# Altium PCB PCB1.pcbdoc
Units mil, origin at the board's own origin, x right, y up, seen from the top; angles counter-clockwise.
Board outline 2952.76 x 2952.76 mil, 2 copper layers (Top Layer, Bottom Layer), stack 62.206 mil thick; 24 components, 35 nets, 97 pads, 20 vias.
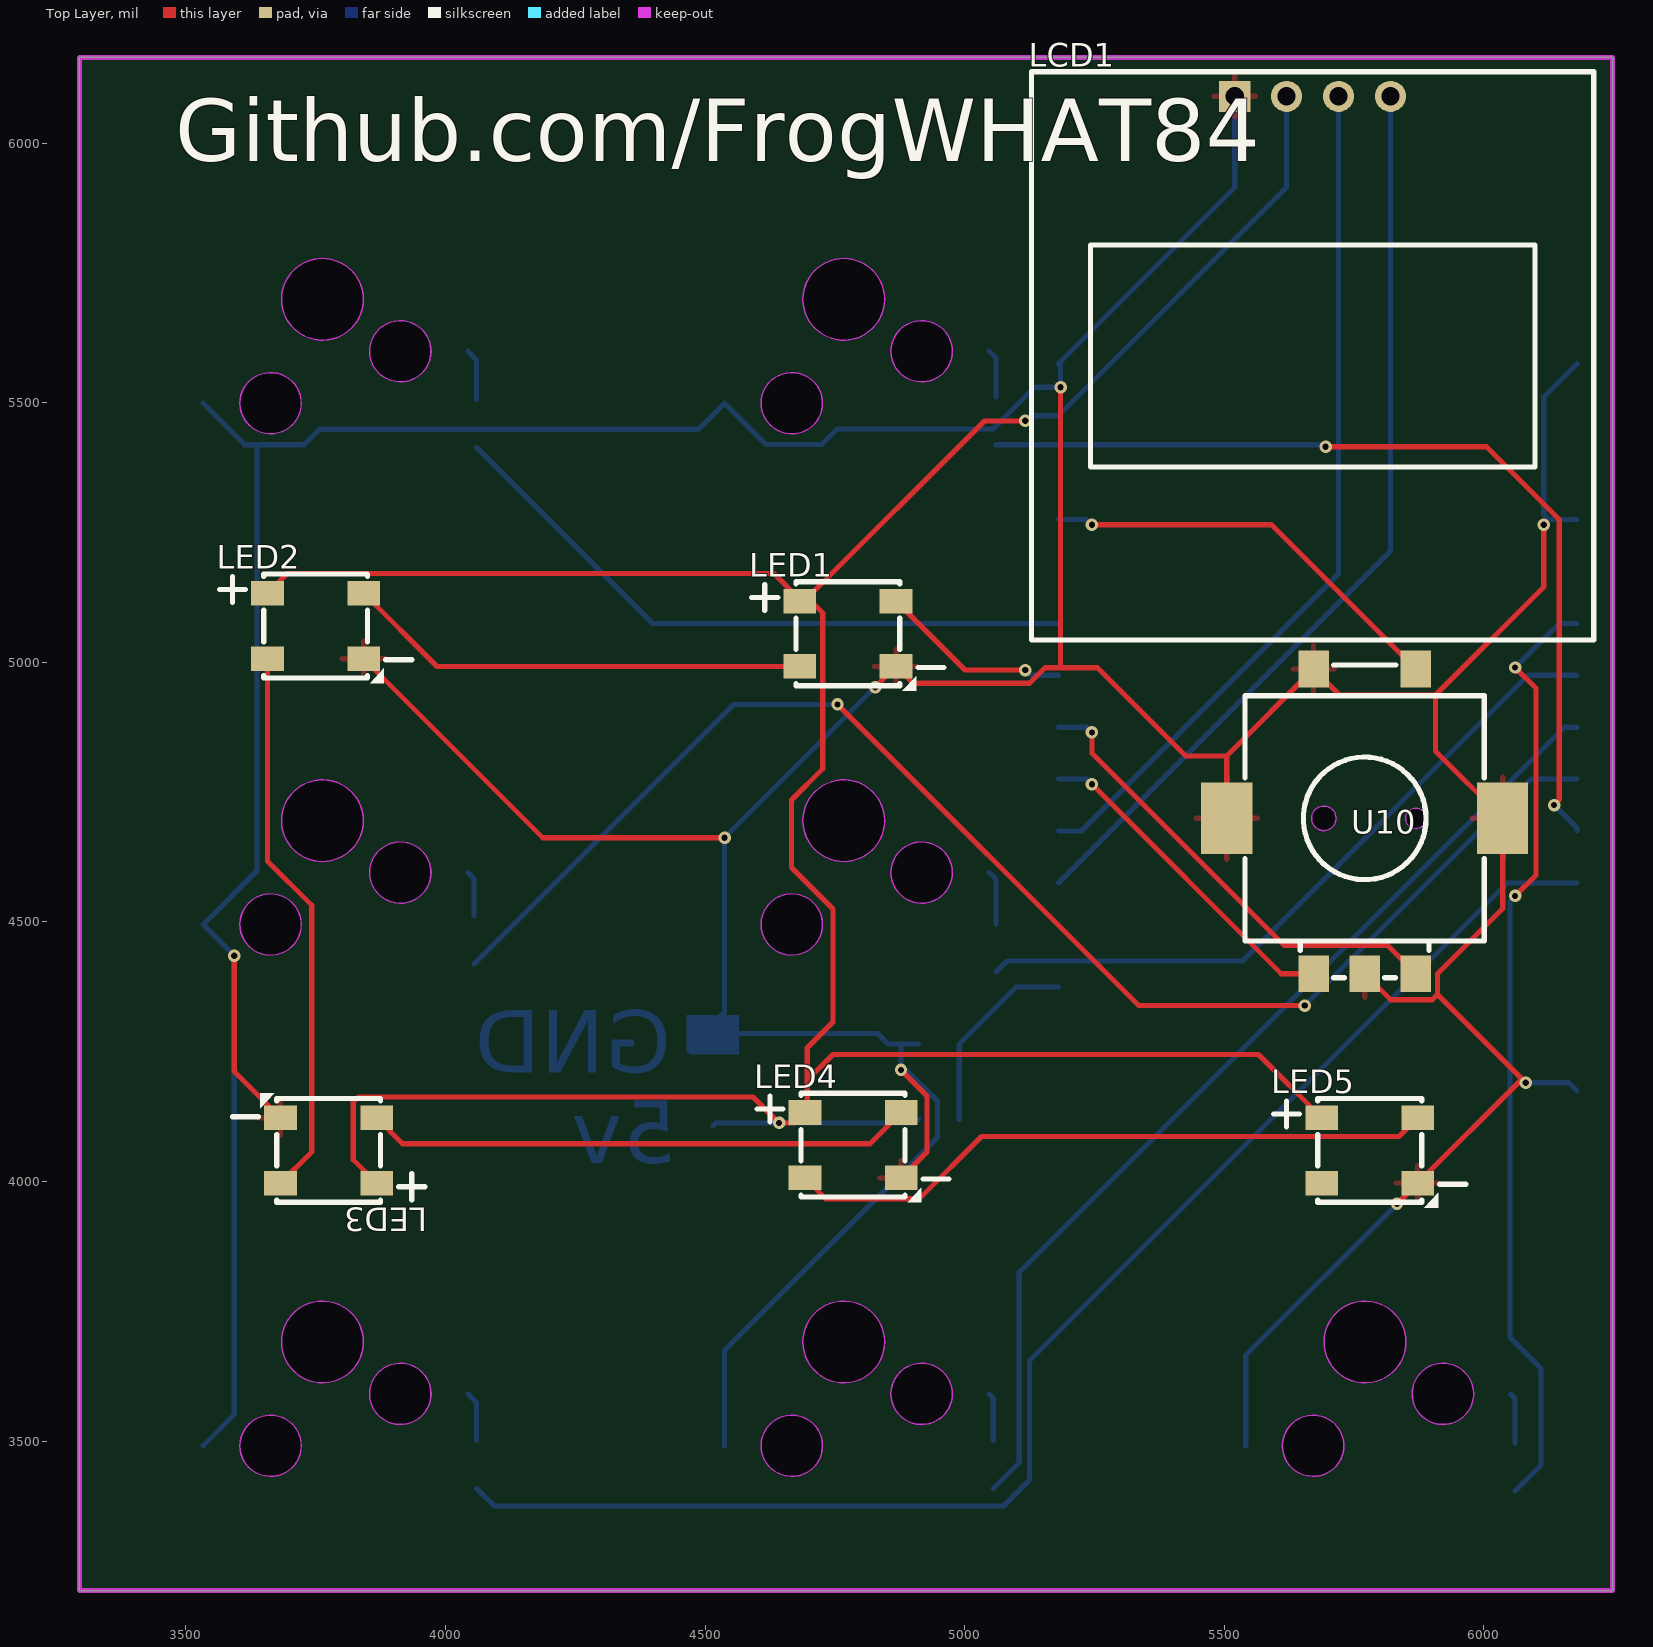
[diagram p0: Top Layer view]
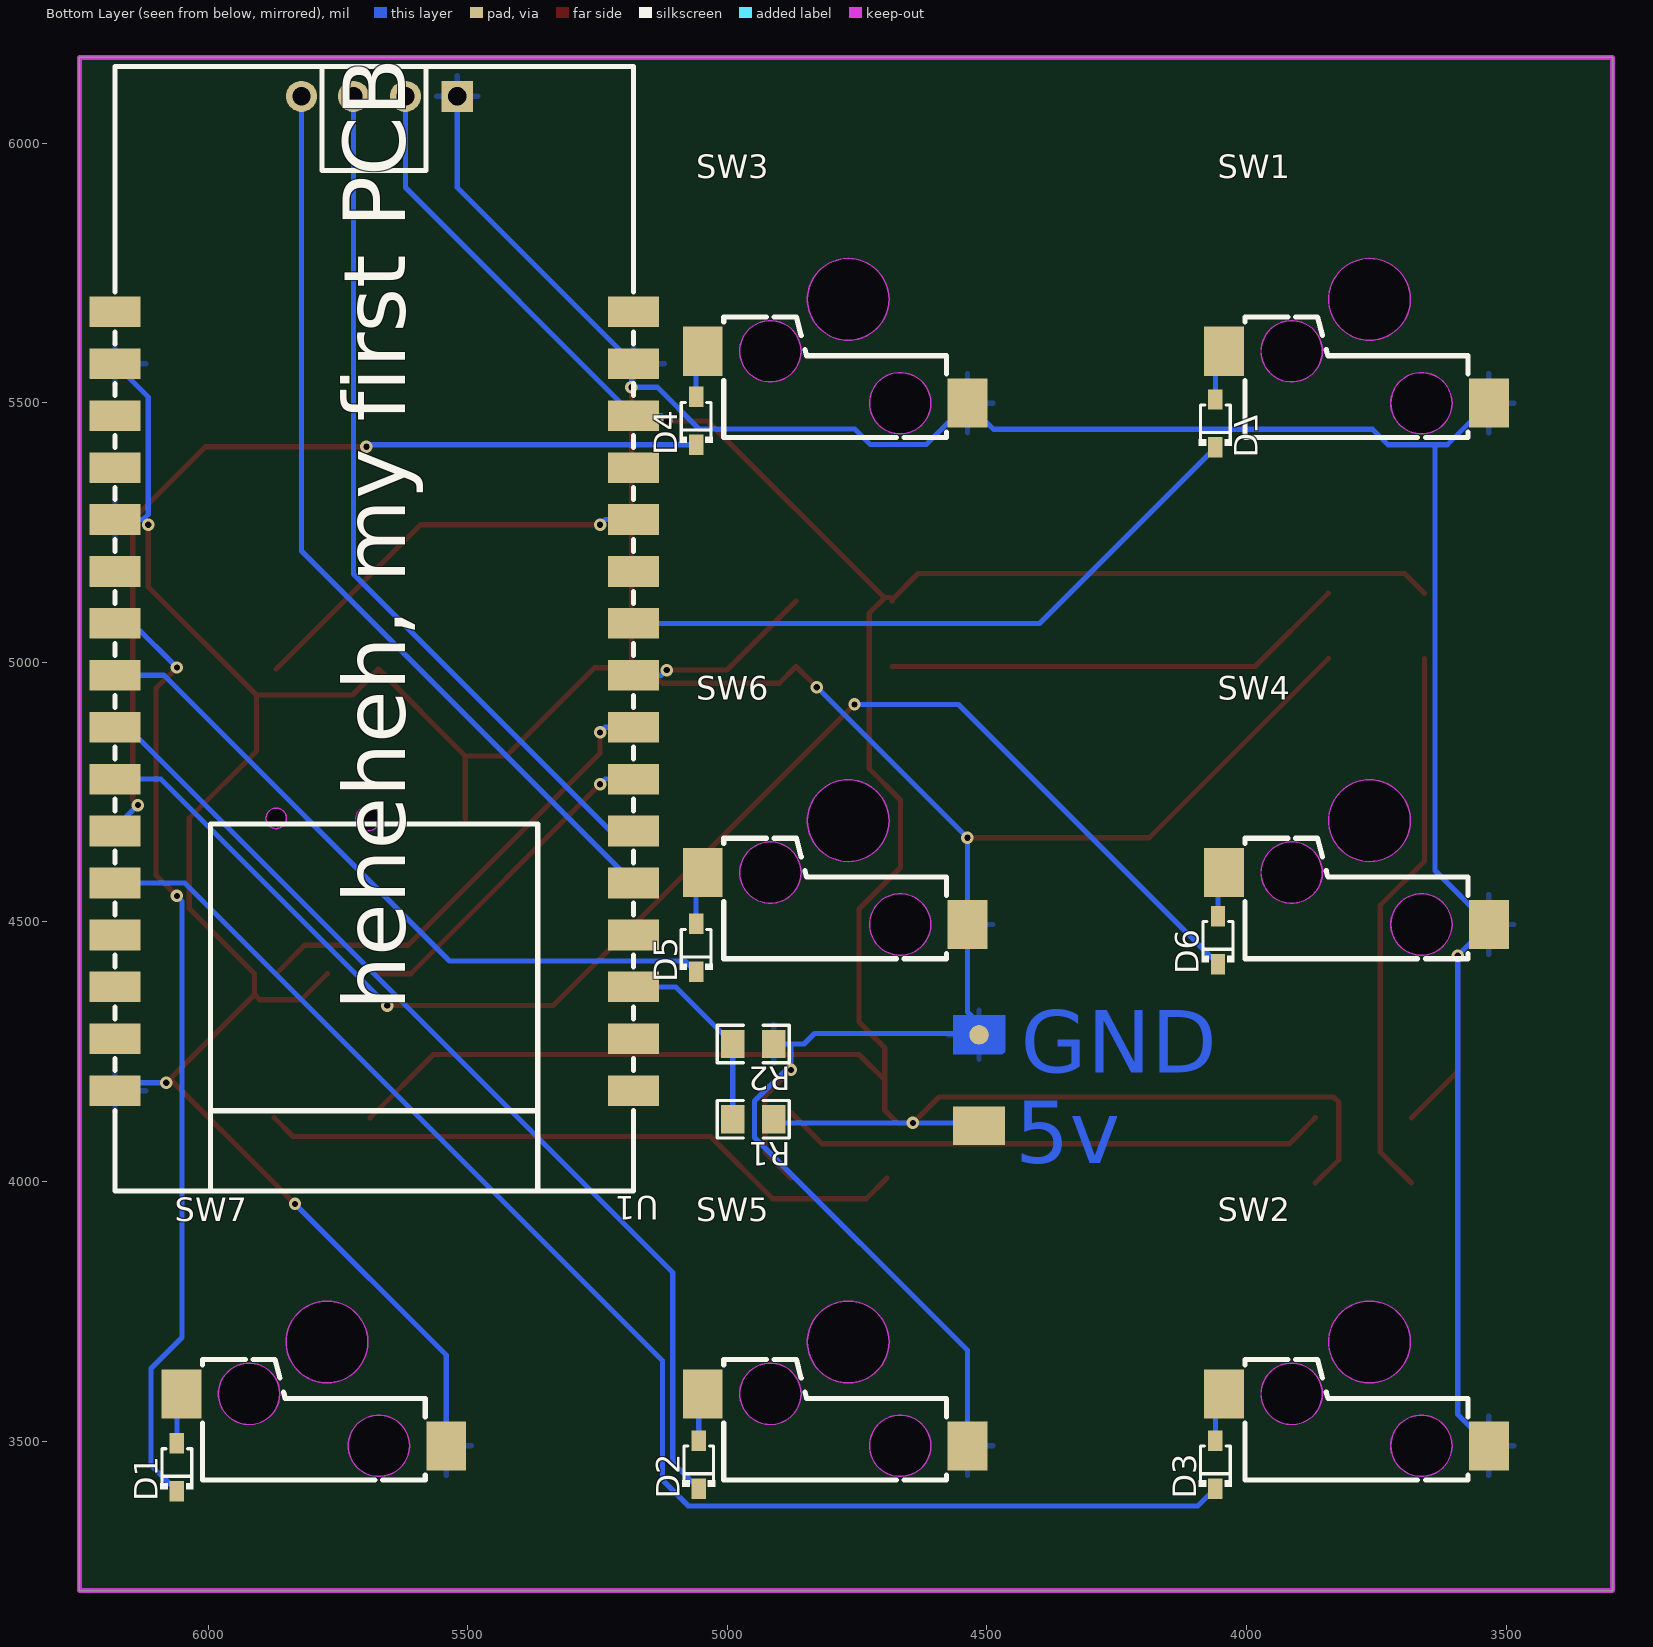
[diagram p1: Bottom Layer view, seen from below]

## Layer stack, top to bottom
Top Solder Mask Layer: solder mask 0.394, Dk 3.3
Top Layer: signal copper 1.379
Dielectric1: surface 59.449, FR4, Dk 4.5
Bottom Layer: signal copper 1.378
Bottom Solder Mask Layer: solder mask 0.394, Dk 3.3

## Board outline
3295,6165 3295,3212.24 6247.76,3212.24 6247.76,6165

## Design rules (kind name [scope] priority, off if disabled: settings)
BoardOutlineClearance copperThickness1oz [All] p0: genericclearance=10 ignorepadtopadclearanceinfootprint=FALSE except(0: Arc-SplitContinuation Track-SplitContinuation SMDPad-SplitContinuation THPad-SplitContinuation Via-SplitContinuation Fill-SplitContinuation Poly-SplitContinuation Region-SplitContinuation Text-SplitContinuation)
BoardOutlineClearance copperThickness2oz [All] p0: genericclearance=10 ignorepadtopadclearanceinfootprint=FALSE except(0: Arc-SplitContinuation Track-SplitContinuation SMDPad-SplitContinuation THPad-SplitContinuation Via-SplitContinuation Fill-SplitContinuation Poly-SplitContinuation Region-SplitContinuation Text-SplitContinuation)
BoardOutlineClearance otherClearance [All] p0: genericclearance=10 ignorepadtopadclearanceinfootprint=FALSE except(0: Arc-SplitContinuation Track-SplitContinuation SMDPad-SplitContinuation THPad-SplitContinuation Via-SplitContinuation Fill-SplitContinuation Poly-SplitContinuation Region-SplitContinuation Text-SplitContinuation)
Clearance copperThickness1oz [All] p1: gap=7 ignorepadtopadclearanceinfootprint=FALSE
Clearance copperThickness2oz [(InNet('+5V'))] p1: gap=7 ignorepadtopadclearanceinfootprint=FALSE
Clearance otherClearance [All] p1: gap=7 ignorepadtopadclearanceinfootprint=FALSE
DiffPairsRouting differentialPair [All] p1: maxuncoupledlength=10 minlimit=6 maxlimit=Infinity mostfreqgap=6 toplayer_minwidth=5 toplayer_prefwidth=10 toplayer_maxwidth=100 bottomlayer_minwidth=5 bottomlayer_prefwidth=10 bottomlayer_maxwidth=100
PasteMaskExpansion pasteMaskExpansion [All] p1: expansion=0
PlaneConnect innerPlane [All] p1: planeconnectstyle=Relief reliefexpansion=20 reliefentries=4 reliefconductorwidth=10 reliefairgap=10
PolygonConnect copperRegion [All] p1: connectstyle=Relief reliefentries=4 reliefconductorwidth=10 polygonreliefangle="90 Angle" airgapwidth=10
RoutingVias viaSize [All] p1: viastyle="Through Hole" holewidth=12.0078 minholewidth=11.811 maxholewidth=248.0314 width=12.0078 minwidth=11.811 maxwidth=248.0314
SolderMaskExpansion solderMaskExpansion [IsVia] p1: useseparateexpansions=TRUE expansion=-1000 expansionbottom=-1000
SolderMaskExpansion solderMaskExpansion [All] p2: useseparateexpansions=TRUE expansion=2 expansionbottom=2
Width copperThickness1oz [All] p1: maxlimit=100 minlimit=5 preferedwidth=10
Width copperThickness2oz [All] p1: maxlimit=100 minlimit=8 preferedwidth=10

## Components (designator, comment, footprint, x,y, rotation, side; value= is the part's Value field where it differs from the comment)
D1 "1N4148WS" SOD-323_L1.8-W1.3-LS2.5-RD#1 6060,3450 r90 bottom
D2 "1N4148WS" SOD-323_L1.8-W1.3-LS2.5-RD#1 5055,3455 r90 bottom
D3 "1N4148WS" SOD-323_L1.8-W1.3-LS2.5-RD#1 4060,3455 r90 bottom
D4 "1N4148WS" SOD-323_L1.8-W1.3-LS2.5-RD#1 5060,5465 r90 bottom
D5 "1N4148WS" SOD-323_L1.8-W1.3-LS2.5-RD#1 5060,4450 r90 bottom
D6 "1N4148WS" SOD-323_L1.8-W1.3-LS2.5-RD#1 4055,4465 r90 bottom
D7 "1N4148WS" SOD-323_L1.8-W1.3-LS2.5-RD#2 4060,5460 r270 bottom
LCD1 "SSD1306" SSD1306 5640,5595 r0 top
LED1 "WS2812B-V6" LED-SMD_4P-L5.0-W5.0-TL-A 4775,5055 r0 top
LED2 "WS2812B-V6" LED-SMD_4P-L5.0-W5.0-TL-A 3750,5070 r0 top
LED3 "WS2812B-V6" LED-SMD_4P-L5.0-W5.0-TL-A 3775,4060 r180 top
LED4 "WS2812B-V6" LED-SMD_4P-L5.0-W5.0-TL-A 4785,4070 r0 top
LED5 "WS2812B-V6" LED-SMD_4P-L5.0-W5.0-TL-A 5780,4060 r0 top
R1 "100K" R0805 4950,4120 r0 bottom
R2 "100K" R0805 4950,4265 r0 bottom
SW1 "SW-5" SW-SMD_KAILH-SOCKET_C9900019772 3762.44,5697.56 r180 bottom
SW2 "SW-5" SW-SMD_KAILH-SOCKET_C9900019772 3762.44,3689.68 r180 bottom
SW3 "SW-5" SW-SMD_KAILH-SOCKET_C9900019772 4766.38,5697.56 r180 bottom
SW4 "SW-5" SW-SMD_KAILH-SOCKET_C9900019772 3762.44,4693.62 r180 bottom
SW5 "SW-5" SW-SMD_KAILH-SOCKET_C9900019772 4766.38,3689.68 r180 bottom
SW6 "SW-5" SW-SMD_KAILH-SOCKET_C9900019772 4766.38,4693.62 r180 bottom
SW7 "SW-5" SW-SMD_KAILH-SOCKET_C9900019772 5770.31,3689.68 r180 bottom
U1 "ESP32-C6-DEV-KIT-N8 COPY" COMM-SMD_L55.0-W25.4_ESP32-C6-DEV-KIT-N8 5680,4925 r0 bottom
U10 "EC1106S" SW-SMD_EC1106S 5770.31,4693.62 r0 top

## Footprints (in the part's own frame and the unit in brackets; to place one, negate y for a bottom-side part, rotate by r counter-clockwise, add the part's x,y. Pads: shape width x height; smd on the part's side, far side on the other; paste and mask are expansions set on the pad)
COMM-SMD_L55.0-W25.4_ESP32-C6-DEV-KIT-N8 [mm]
  rect 2.5x1.5 smd paste+0 mask+0.051: 1(-12.68,19.05) 2(-12.68,16.51) 3(-12.68,13.97) 4(-12.68,11.43) 5(-12.68,8.89) 6(-12.68,6.35) 7(-12.68,3.81) 8(-12.68,1.27) 9(-12.68,-1.27) 10(-12.68,-3.81) 11(-12.68,-6.35) 12(-12.68,-8.89) 13(-12.68,-11.43) 14(-12.68,-13.97) 15(-12.68,-16.51) 16(-12.68,-19.05) 17(12.68,-19.05) 18(12.68,-16.51) 19(12.68,-13.97) 20(12.68,-11.43) 21(12.68,-8.89) 22(12.68,-6.35) 23(12.68,-3.81) 24(12.68,-1.27) 25(12.68,1.27) 26(12.68,3.81) 27(12.68,6.35) 28(12.68,8.89) 29(12.68,11.43) 30(12.68,13.97) 31(12.68,16.51) 32(12.68,19.05)
  silkscreen extent -12.68,-31.05 12.68,23.95
LED-SMD_4P-L5.0-W5.0-TL-A [mm]
  rect 1.6x1.2 smd paste+0 mask+0.05: 1(-2.35,1.6) 2(-2.35,-1.6) 3(2.35,-1.6) 4(2.35,1.6)
  silkscreen extent -4.7,-2.79 4.7,2.54
R0805 [mm]
  rect 1.133x1.377 smd paste-100 mask+0.051: 1(-1,0) 2(1,0)
  silkscreen extent -1.76,-0.92 1.76,0.92
SOD-323_L1.8-W1.3-LS2.5-RD#1 [mm]
  rect 1x0.7 smd: 1(-1.172,0) 2(1.172,0)
  silkscreen extent -1.08,-0.8 0.9,0.8
SOD-323_L1.8-W1.3-LS2.5-RD#2 [mm]
  rect 1x0.7 smd: 1(1.172,0) 2(-1.172,0)
  silkscreen extent -0.9,-0.8 1.08,0.8
SSD1306 [mil]
  rect 60x60 hole 35 paste+0 mask+4: 1(-120,495)
  round 60 hole 35 paste+0 mask+4: 2(-20,495) 3(80,495) 4(180,495)
  silkscreen extent -511,-552 571,542
SW-SMD_EC1106S [mm]
  rect 1.5x1.8 smd paste+0 mask+0.05: 1(-2.5,-7.45) 2(0,-7.45) 3(2.5,-7.45) 4(2.5,7.45) 5(-2.5,7.45)
  rect 2.5x3.5 smd paste+0 mask+0.05: 6(-6.75,0.15) 7(6.75,0.15)
  Board Outline Layer circle w0.003: c-2,0.15 r0.6
  Board Outline Layer circle w0.003: c2.5,0.15 r0.5
  Board Outline Layer region: -1.4,0.15 -1.459,-0.11 -1.626,-0.319 -1.866,-0.435 -2.134,-0.435 -2.374,-0.319 -2.541,-0.11 -2.6,0.15 -2.6,0.15 -2.541,0.41 -2.374,0.619 -2.134,0.735 -1.866,0.735 -1.626,0.619 -1.459,0.41 -1.4,0.15
  Board Outline Layer region: -1.4,0.15 -1.409,0.046 -1.436,-0.055 -1.48,-0.15 -1.54,-0.236 -1.614,-0.31 -1.7,-0.37 -1.795,-0.414 -1.896,-0.441 -2,-0.45 -2.104,-0.441 -2.205,-0.414 -2.3,-0.37 -2.386,-0.31 -2.46,-0.236 -2.52,-0.15 -2.564,-0.055 -2.591,0.046 -2.6,0.15 -2.591,0.254 -2.564,0.355 -2.52,0.45 -2.46,0.536 -2.386,0.61 -2.3,0.67 -2.205,0.714 -2.104,0.741 -2,0.75 -1.896,0.741 -1.795,0.714 -1.7,0.67 -1.614,0.61 -1.54,0.536 -1.48,0.45 -1.436,0.355 -1.409,0.254
  Board Outline Layer region: 3,0.15 2.951,-0.067 2.812,-0.241 2.611,-0.337 2.389,-0.337 2.188,-0.241 2.05,-0.067 2,0.15 2,0.15 2.05,0.367 2.188,0.541 2.389,0.637 2.611,0.637 2.812,0.541 2.951,0.367 3,0.15
  Board Outline Layer region: 3,0.15 2.991,0.052 2.962,-0.041 2.916,-0.128 2.854,-0.204 2.778,-0.266 2.691,-0.312 2.598,-0.34 2.5,-0.35 2.403,-0.34 2.309,-0.312 2.222,-0.266 2.147,-0.204 2.084,-0.128 2.038,-0.041 2.01,0.052 2,0.15 2.01,0.248 2.038,0.341 2.084,0.428 2.147,0.504 2.222,0.566 2.309,0.612 2.403,0.64 2.5,0.65 2.598,0.64 2.691,0.612 2.778,0.566 2.854,0.504 2.916,0.428 2.962,0.341 2.991,0.248
  Multi-Layer board cut-out: -1.4,0.15 -1.459,-0.11 -1.626,-0.319 -1.866,-0.435 -2.134,-0.435 -2.374,-0.319 -2.541,-0.11 -2.6,0.15 -2.6,0.15 -2.541,0.41 -2.374,0.619 -2.134,0.735 -1.866,0.735 -1.626,0.619 -1.459,0.41 -1.4,0.15
  Multi-Layer board cut-out: 3,0.15 2.951,-0.067 2.812,-0.241 2.611,-0.337 2.389,-0.337 2.188,-0.241 2.05,-0.067 2,0.15 2,0.15 2.05,0.367 2.188,0.541 2.389,0.637 2.611,0.637 2.812,0.541 2.951,0.367 3,0.15
  silkscreen extent -5.85,-7.65 5.85,7.65
SW-SMD_KAILH-SOCKET_C9900019772 [mm]
  rect 1.95x2.4 smd paste+0 mask+0.05: 1(-7.132,-2.503) 2(5.818,-5.043)
  Board Outline Layer circle w0.003: c-0.017,0.037 r2
  Board Outline Layer circle w0.003: c-3.827,-2.503 r1.5
  Board Outline Layer circle w0.003: c2.523,-5.043 r1.5
  Board Outline Layer region: -2.017,0.037 -1.819,-0.831 -1.264,-1.527 -0.462,-1.913 0.428,-1.913 1.23,-1.527 1.785,-0.831 1.983,0.037 1.983,0.037 1.785,0.905 1.23,1.601 0.428,1.987 -0.462,1.987 -1.264,1.601 -1.819,0.905 -2.017,0.037
  Board Outline Layer region: -2.017,0.037 -2.007,-0.159 -1.978,-0.353 -1.931,-0.544 -1.865,-0.728 -1.781,-0.906 -1.68,-1.074 -1.563,-1.232 -1.431,-1.377 -1.286,-1.509 -1.128,-1.626 -0.96,-1.727 -0.782,-1.811 -0.597,-1.877 -0.407,-1.925 -0.213,-1.953 -0.017,-1.963 0.179,-1.953 0.373,-1.925 0.564,-1.877 0.748,-1.811 0.926,-1.727 1.094,-1.626 1.252,-1.509 1.397,-1.377 1.529,-1.232 1.646,-1.074 1.747,-0.906 1.831,-0.728 1.897,-0.544 1.945,-0.353 1.973,-0.159 1.983,0.037 1.973,0.233 1.945,0.427 1.897,0.618 1.831,0.802 1.747,0.98 1.646,1.148 1.529,1.306 1.397,1.451 1.252,1.583 1.094,1.7 0.926,1.801 0.748,1.885 0.564,1.951 0.373,1.999 0.179,2.027 -0.017,2.037 -0.213,2.027 -0.407,1.999 -0.597,1.951 -0.782,1.885 -0.96,1.801 -1.128,1.7 -1.286,1.583 -1.431,1.451 -1.563,1.306 -1.68,1.148 -1.781,0.98 -1.865,0.802 -1.931,0.618 -1.978,0.427 -2.007,0.233
  Board Outline Layer region: -5.327,-2.503 -5.178,-3.154 -4.762,-3.676 -4.161,-3.965 -3.493,-3.965 -2.892,-3.676 -2.475,-3.154 -2.327,-2.503 -2.327,-2.503 -2.475,-1.852 -2.892,-1.33 -3.493,-1.041 -4.161,-1.041 -4.762,-1.33 -5.178,-1.852 -5.327,-2.503
  Board Outline Layer region: -5.327,-2.503 -5.317,-2.677 -5.286,-2.849 -5.236,-3.016 -5.167,-3.176 -5.08,-3.327 -4.976,-3.467 -4.856,-3.594 -4.723,-3.706 -4.577,-3.802 -4.421,-3.88 -4.257,-3.94 -4.087,-3.98 -3.914,-4 -3.74,-4 -3.566,-3.98 -3.397,-3.94 -3.233,-3.88 -3.077,-3.802 -2.931,-3.706 -2.798,-3.594 -2.678,-3.467 -2.574,-3.327 -2.486,-3.176 -2.417,-3.016 -2.367,-2.849 -2.337,-2.677 -2.327,-2.503 -2.337,-2.329 -2.367,-2.157 -2.417,-1.99 -2.486,-1.83 -2.574,-1.679 -2.678,-1.539 -2.798,-1.412 -2.931,-1.3 -3.077,-1.204 -3.233,-1.126 -3.397,-1.066 -3.566,-1.026 -3.74,-1.006 -3.914,-1.006 -4.087,-1.026 -4.257,-1.066 -4.421,-1.126 -4.577,-1.204 -4.723,-1.3 -4.856,-1.412 -4.976,-1.539 -5.08,-1.679 -5.167,-1.83 -5.236,-1.99 -5.286,-2.157 -5.317,-2.329
  Board Outline Layer region: 1.023,-5.043 1.172,-5.694 1.588,-6.216 2.189,-6.505 2.857,-6.505 3.458,-6.216 3.875,-5.694 4.023,-5.043 4.023,-5.043 3.875,-4.392 3.458,-3.87 2.857,-3.581 2.189,-3.581 1.588,-3.87 1.172,-4.392 1.023,-5.043
  Board Outline Layer region: 1.023,-5.043 1.033,-5.217 1.064,-5.389 1.114,-5.556 1.183,-5.716 1.27,-5.867 1.374,-6.007 1.494,-6.134 1.627,-6.246 1.773,-6.342 1.929,-6.42 2.093,-6.48 2.263,-6.52 2.436,-6.54 2.61,-6.54 2.784,-6.52 2.953,-6.48 3.117,-6.42 3.273,-6.342 3.419,-6.246 3.552,-6.134 3.672,-6.007 3.776,-5.867 3.864,-5.716 3.933,-5.556 3.983,-5.389 4.013,-5.217 4.023,-5.043 4.013,-4.869 3.983,-4.697 3.933,-4.53 3.864,-4.37 3.776,-4.219 3.672,-4.079 3.552,-3.952 3.419,-3.84 3.273,-3.744 3.117,-3.666 2.953,-3.606 2.784,-3.566 2.61,-3.546 2.436,-3.546 2.263,-3.566 2.093,-3.606 1.929,-3.666 1.773,-3.744 1.627,-3.84 1.494,-3.952 1.374,-4.079 1.27,-4.219 1.183,-4.37 1.114,-4.53 1.064,-4.697 1.033,-4.869
  Multi-Layer board cut-out: -2.017,0.037 -1.819,-0.831 -1.264,-1.527 -0.462,-1.913 0.428,-1.913 1.23,-1.527 1.785,-0.831 1.983,0.037 1.983,0.037 1.785,0.905 1.23,1.601 0.428,1.987 -0.462,1.987 -1.264,1.601 -1.819,0.905 -2.017,0.037
  Multi-Layer board cut-out: -5.327,-2.503 -5.178,-3.154 -4.762,-3.676 -4.161,-3.965 -3.493,-3.965 -2.892,-3.676 -2.475,-3.154 -2.327,-2.503 -2.327,-2.503 -2.475,-1.852 -2.892,-1.33 -3.493,-1.041 -4.161,-1.041 -4.762,-1.33 -5.178,-1.852 -5.327,-2.503
  Multi-Layer board cut-out: 1.023,-5.043 1.172,-5.694 1.588,-6.216 2.189,-6.505 2.857,-6.505 3.458,-6.216 3.875,-5.694 4.023,-5.043 4.023,-5.043 3.875,-4.392 3.458,-3.87 2.857,-3.581 2.189,-3.581 1.588,-3.87 1.172,-4.392 1.023,-5.043
  silkscreen extent -6.11,-6.72 4.79,-0.82

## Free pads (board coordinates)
  round 37.44 smd far side: 1(4515.08,4282.56)
  rect 100x75 smd far side: 2(4515,4107.5)

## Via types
v1: diameter 24.02, hole 12, Top Layer to Bottom Layer, 20 vias

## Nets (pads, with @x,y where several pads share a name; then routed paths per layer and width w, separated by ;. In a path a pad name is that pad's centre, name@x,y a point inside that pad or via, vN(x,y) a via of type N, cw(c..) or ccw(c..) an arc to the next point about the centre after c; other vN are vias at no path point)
$1N48: R1.2 R2.2 U1.3 | length 382
  Bottom Layer w10: R1.2 R2.2 5099.37,4375 U1.3
$1N108: LED1.2 LED2.4 | length 898.4
  Top Layer w10: LED2.4 3983.51,4992 LED1.2
$1N110: LED2.2 LED3.4 | length 1070.1
  Top Layer w10: LED2.2 3657.48,4617 3742.48,4532 3742.48,4057 LED3.4
$1N113: LED3.2 LED4.4 | length 1055.6
  Top Layer w10: LED3.2 3917.52,4073 4817.52,4073 LED4.4
$1N123: LED5.2
$1N128: LED4.2 LED5.4 | length 1261.2
  Top Layer w10: LED4.2 4732.48,3967 4912.48,3967 5032.48,4087 5836.53,4087 LED5.4
$1N129: D7.2 SW1.1 | length 99.8
  Bottom Layer w10: SW1.1 4060,5582.25 D7.2
$1N132: D3.2 SW2.1 | length 96.9
  Bottom Layer w10: SW2.1 4060,3574.37 D3.2
$1N133: D4.2 SW3.1 | length 93.2
  Bottom Layer w10: SW3.1 5060,5586.18 D4.2
$1N136: D6.2 SW4.1 | length 88.8
  Bottom Layer w10: SW4.1 4055,4583.31 D6.2
$1N138: D2.2 SW5.1 | length 93.2
  Bottom Layer w10: SW5.1 5055,3583.31 D2.2
$1N139: D5.2 SW6.1 | length 104.2
  Bottom Layer w10: SW6.1 5060,4582.24 D5.2
$1N141: D1.2 SW7.1 | length 98.7
  Bottom Layer w10: SW7.1 6060,3582.25 D1.2
+5V: LCD1.2 LED1.1 LED2.1 LED3.1 LED4.1 LED5.1 pad.2 R1.1 U1.14 | length 6131.8
  Top Layer w10: LED2.1 3695.39,5170.9 4632.48,5170.9 LED1.1@4682.48,5120.9 ; LED3.1 3822.48,4042.04 3822.48,4153 3832.48,4163 4592.48,4163 v1(4642.48,4113) 4672.48,4113 LED4.1 4696.58,4137.09 4696.58,4195 ; LED1.1 LED1.1@4682.48,5120.9 ; v1(5116.58,5464.99) 5037.84,5464.99 4697.84,5124.99 LED1.1@4696.58,5124.99 ; LED5.1 5565.48,4245 4746.58,4245 4696.58,4195 ; LED1.1@4682.48,5120.9 4686.58,5124.99 LED1.1@4696.58,5124.99 ; 4696.58,4195 4696.58,4257.52 4746.58,4307.52 4746.58,4525 4666.58,4605 4666.58,4734.99 4726.58,4794.99 4726.58,5094.99 LED1.1@4696.58,5124.99
  Bottom Layer w10: pad.2 4520.5,4113 v1(4642.48,4113) 4903.63,4113 R1.1 ; v1(5116.58,5464.99) 5126.58,5474.99 U1.14 5620,5914.21 LCD1.2
GND: LCD1.1 LED1.3 LED2.3 LED3.3 LED4.3 LED5.3 pad.1 R2.1 SW1.2 SW2.2 SW3.2 SW4.2 SW5.2 SW6.2 SW7.2 U1.15 U1.18 U1.21 U1.32 U10.2 U10.5 U10.6 U10.7 | length 13010.8
  Top Layer w10: v1(3593.39,4435.08) 3593.39,4212.09 LED3.3 ; LED2.3 4187.52,4662 v1(4537.52,4662) ; v1(4827.52,4952) LED1.3 4899.93,4959.6 5124.56,4959.6 5154.56,4989.6 5184.56,4989.6 ; v1(4877.32,4215.08) 4927.32,4165.08 4927.32,4056.81 LED4.3 ; v1(5184.56,5529.6) 5184.56,4989.6 ; U10.6 5504.56,4819.6 ; U10.2 5820.31,4350.32 5900.31,4350.32 5910.31,4360.32 ; v1(5832.52,3957) LED5.3 6070.31,4194.8 6070.31,4200.32 ; v1(6080.31,4190.32) 6070.31,4200.32 ; v1(6115,5264.99) 6115,5144.99 5906.93,4936.93 ; 5184.56,4989.6 5255.82,4989.6 5425.82,4819.6 5504.56,4819.6 ; 5504.56,4819.6 U10.5 5721.89,4936.93 5906.93,4936.93 ; 5906.93,4936.93 5906.93,4828.66 U10.7 6036.07,4526.07 5910.31,4400.32 5910.31,4360.32 ; 5910.31,4360.32 6070.31,4200.32
  Bottom Layer w10: SW2.2 3593.39,3551.14 v1(3593.39,4435.08) SW4.2 3637.33,4599.02 3637.33,5419.02 ; SW1.2 3613.39,5419.02 3637.33,5419.02 ; pad.1@4515,4282.5 pad.1@4517.32,4285.08 ; SW5.2 4537.32,3675.08 4947.32,4085.08 4947.32,4155.08 4887.32,4215.08 v1(4877.32,4215.08) 4877.32,4265.01 ; SW6.2 4537.32,4326.34 4517.32,4306.34 pad.1@4517.32,4285.08 ; SW6.2@4537.52,4495.27 v1(4537.52,4662) v1(4827.52,4952) ; R2.1 4877.32,4265.01 ; LCD1.1 5520,5914.21 U1.15 5184.56,5571.22 v1(5184.56,5529.6) 5134.56,5529.6 5054.56,5449.6 4754.56,5449.6 4724.56,5419.6 4616.75,5419.6 SW3.2 4487.32,5449.02 3757.33,5449.02 3727.33,5419.02 3637.33,5419.02 ; SW7.2 5541.26,3665.75 v1(5832.52,3957) ; v1(6080.31,4190.32) 6163.9,4190.32 U1.32 ; v1(6115,5264.99) 6125,5274.99 ; U1.21 6125,5274.99 ; U1.18 6115,5510.78 6115,5284.99 6125,5274.99 ; pad.1@4517.32,4285.08 4832.22,4285.08 4852.28,4265.01 4877.32,4265.01
GPIO_0: U1.7 U10.1 | length 646.3
  Top Layer w10: v1(5245,4765) 5609.68,4400.32 U10.1
  Bottom Layer w10: U1.7 5235,4775 v1(5245,4765)
GPIO_1: U1.8 U10.3 | length 908
  Top Layer w10: v1(5245,4865) 5245,4825 5615,4455 5814.05,4455 U10.3
  Bottom Layer w10: U1.8 5235,4875 v1(5245,4865)
GPIO_2: U1.12 U10.4 | length 807.3
  Top Layer w10: v1(5245,5264.99) 5590.67,5264.99 U10.4
  Bottom Layer w10: U1.12 5235,5274.99 v1(5245,5264.99)
GPIO_6: LCD1.4 U1.5 | length 1779.8
  Bottom Layer w10: U1.5 5820,5214.21 LCD1.4
GPIO_7: LCD1.3 U1.6 | length 1664.2
  Bottom Layer w10: U1.6 5225,4675 5720,5170 LCD1.3
GPIO_8: LED1.4 U1.9 | length 372.5
  Top Layer w10: LED1.4 5000.51,4985 v1(5116.58,4985)
  Bottom Layer w10: v1(5116.58,4985) 5126.58,4975 U1.9
Kalih_1: D1.1 U1.23
KALIH_1:  | length 1823.4
  Top Layer w10: v1(6060,4550) 6100,4590 6100,4950 v1(6060,4990)
  Bottom Layer w10: 6060,3403.84 6110,3453.84 6110,3640.01 6050,3700 6050,4540 v1(6060,4550) ; v1(6060,4990) 6145,5075 6179.21,5075
Kalih_2: D5.1 U1.24
KALIH_2:  | length 1355.8
  Bottom Layer w10: 5060,4403.84 5081.17,4425 5535,4425 6085,4975 6179.21,4975
Kalih_3: D2.1 U1.25
KALIH_3:  | length 1946
  Bottom Layer w10: 5055,3408.84 5105,3458.84 5105,3825 6155,4875 6179.21,4875
Kalih_4: D6.1 U1.26
KALIH_4:  | length 2752.2
  Top Layer w10: v1(4755,4918.84) 5335,4338.84 v1(5655,4338.84)
  Bottom Layer w10: 4055,4418.84 4555,4918.84 v1(4755,4918.84) ; v1(5655,4338.84) 6091.16,4775 6179.21,4775
Kalih_5: D4.1 U1.27
KALIH_5:  | length 1767
  Top Layer w10: v1(5695,5415) 6005,5415 6145,5275 6145,4735 v1(6135,4725)
  Bottom Layer w10: 5060,5418.84 5691.16,5418.84 v1(5695,5415) ; v1(6135,4725) 6179.21,4680.79 6179.21,4675
Kalih_6: D3.1 U1.28
KALIH_6:  | length 2765
  Bottom Layer w10: 4060,3408.84 4093.83,3375.01 5075,3375.01 5125,3425.01 5125,3655.01 6045,4575 6179.21,4575
Kalih_7: D7.1 U1.10
KALIH_7:  | length 1261.1
  Bottom Layer w10: 4060,5413.84 4398.84,5075 5180.79,5075
pads on no net: U1.1 U1.2 U1.4 U1.11 U1.13 U1.16 U1.17 U1.19 U1.20 U1.22 U1.29 U1.30 U1.31

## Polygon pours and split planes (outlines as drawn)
GND on Top Layer (solid, pour order 0): 3240,6235 3240,3170 6315,3170 6315,6235
GND on Bottom Layer (solid, pour order 2): 3150,6275 3150,3135 6280,3135 6280,6275
GND on Bottom Layer (solid, remove dead copper, pour order 4): 3000,6435 3000,3000 6585,3000 6585,6435

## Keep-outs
Board Outline Layer:
  the board outline again, w10

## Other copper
Bottom Layer:
  region net GND: 4465,4320 4565,4320 4565,4245 4470,4245 4465,4250
  text "GND" at 4435,4210 h120
  text "5v" at 4445,4035 h120

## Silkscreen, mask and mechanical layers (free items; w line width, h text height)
Top Silkscreen Layer:
  text "Github.com/FrogWHAT84" at 3480,5965 h120
Bottom Silkscreen Layer:
  text "heheheh, my first PCB" at 5620,4330 h120 r270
